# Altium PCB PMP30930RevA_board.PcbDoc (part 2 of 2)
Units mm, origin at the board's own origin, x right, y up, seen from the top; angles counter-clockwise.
Board outline 59.18 x 142.49 mm, 4 copper layers (Top Layer, Layer 1, Layer 2, Bottom Layer), stack 1.787 mm thick; 111 components, 60 nets, 253 pads, 640 vias.
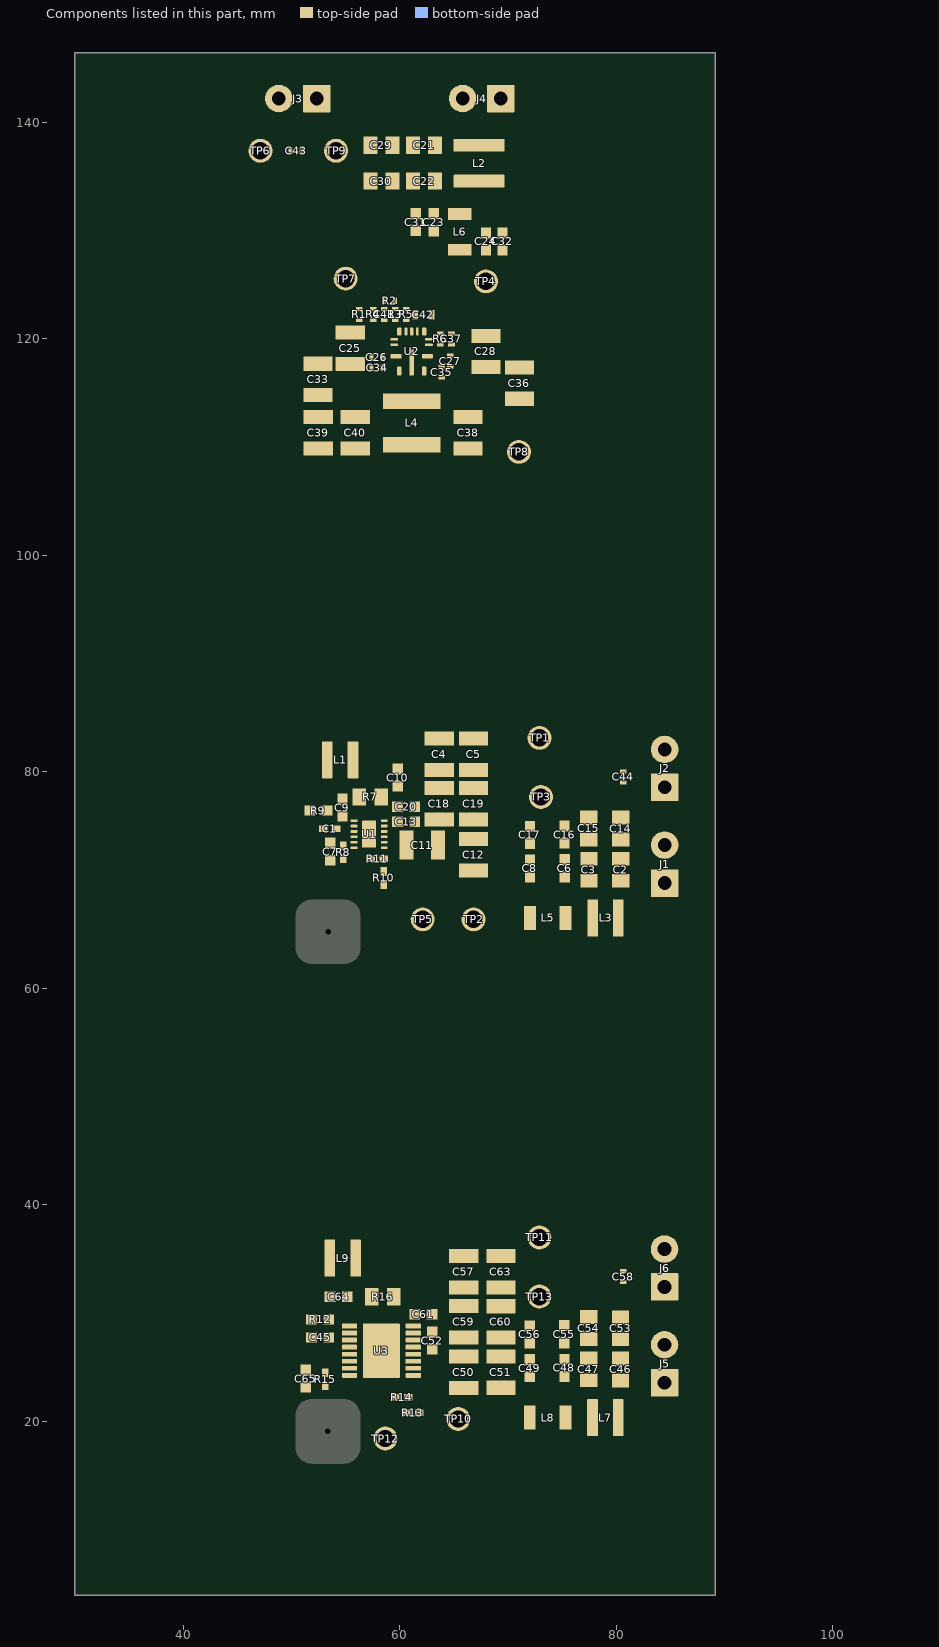
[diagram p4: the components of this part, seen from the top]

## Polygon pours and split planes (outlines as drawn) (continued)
NetC64_1 on Top Layer "NETC64_1_L01_P148" (solid, pour order 148): 54.455,28.056 cw(c55.096,28.773) 54.229,28.356 ccw(c53.617,27.745) 53.616,28.61 53.467,28.61 cw(c53.467,29.223) 53.033,28.79 52.884,28.938 cw(c53.318,29.372) 52.705,29.372 52.705,35.976 cw(c53.752,36.05) 52.959,36.738 cw(c53.336,36.354) 53.341,36.893 53.802,36.893 cw(c53.765,36.457) 54.1,36.738 cw(c53.31,36.049) 54.356,35.976 54.356,30.546 ccw(c55.656,30.546) 54.737,29.626 ccw(c55.35,30.239) 55.35,29.372 55.7,29.372 cw(c55.701,28.939) 56.007,29.245 56.044,29.208 cw(c55.828,28.992) 56.134,28.991 56.134,28.037 cw(c55.97,28.037) 56.086,27.921 cw(c56.001,28.005) 56.001,27.886 54.893,27.886 cw(c54.879,28.5)
GND_C on Top Layer "GND_C_L01_P147" (solid, pour order 147): 84.083,25.562 cw(c84.083,27.73) 82.55,26.197 82.237,26.51 cw(c83.321,27.594) 81.788,27.594 81.788,27.69 ccw(c80.487,27.69) 81.407,28.61 ccw(c81.1,28.304) 81.1,28.737 76.94,28.737 ccw(c76.94,27.87) 76.327,28.483 76.305,28.461 cw(c75.438,29.328) 75.438,28.102 72.092,28.102 cw(c72.092,29.836) 70.866,28.61 ccw(c70.586,28.367) 70.612,28.737 69.85,28.737 69.85,33.182 81.704,33.182 ccw(c81.704,34.917) 82.931,33.69 cw(c83.544,33.077) 83.544,33.944 85.493,33.944 cw(c85.493,33.077) 86.106,33.69 cw(c85.493,33.077) 86.36,33.077 86.36,26.863 cw(c85.059,26.863) 85.979,25.943 cw(c85.059,26.863) 85.059,25.562
NetC49_2 on Top Layer "NETC49_2_L01_P146" (solid, pour order 146): 71.538,25.172 cw(c71.559,25.258) 71.483,25.212 cw(c71.625,25.323) 71.447,25.347 71.447,27.731 cw(c71.553,27.723) 71.483,27.804 cw(c71.554,27.72) 71.564,27.829 72.466,27.829 cw(c72.459,27.714) 72.546,27.789 cw(c72.452,27.712) 72.573,27.698 72.573,25.333 cw(c72.405,25.33) 72.525,25.212 cw(c72.433,25.297) 72.437,25.172
NetC48_2 on Top Layer "NETC48_2_L01_P145" (solid, pour order 145): 74.792,25.126 cw(c74.792,25.272) 74.689,25.169 cw(c74.802,25.296) 74.632,25.286 74.632,27.754 cw(c74.738,27.746) 74.668,27.826 cw(c74.739,27.743) 74.748,27.852 75.651,27.852 cw(c75.643,27.737) 75.73,27.812 cw(c75.636,27.735) 75.757,27.721 75.759,25.248 cw(c75.644,25.257) 75.719,25.169 cw(c75.608,25.29) 75.6,25.126
NetC47_2 on Top Layer "NETC47_2_L01_P144" (solid, pour order 144): 77.597,28.356 76.751,28.356 ccw(c76.751,28.129) 76.591,28.29 ccw(c76.711,28.169) 76.541,28.169 76.541,25.229 ccw(c76.734,25.229) 76.598,25.093 ccw(c76.702,25.197) 76.702,25.05 78.224,25.05 ccw(c78.224,25.231) 78.352,25.103 ccw(c78.216,25.239) 78.409,25.239 78.409,28.133 ccw(c78.186,28.133) 78.343,28.291 ccw(c78.184,28.131) 78.184,28.357 78.141,28.357
NetC46_2 on Top Layer "NETC46_2_L01_P143" (solid, pour order 143): 80.518,28.356 79.672,28.356 ccw(c79.672,28.129) 79.512,28.29 ccw(c79.632,28.169) 79.462,28.169 79.462,25.229 ccw(c79.655,25.229) 79.519,25.093 ccw(c79.623,25.197) 79.623,25.05 81.145,25.05 ccw(c81.145,25.231) 81.273,25.103 ccw(c81.137,25.239) 81.33,25.239 81.33,28.133 ccw(c81.107,28.133) 81.264,28.291 ccw(c81.105,28.131) 81.105,28.357 81.062,28.357
NetC46_1 on Top Layer "NETC46_1_L01_P142" (solid, pour order 142): 79.808,24.673 ccw(c79.808,24.239) 79.502,24.546 ccw(c79.808,24.239) 79.375,24.239 79.375,18.884 ccw(c79.808,18.884) 79.502,18.577 ccw(c79.808,18.884) 79.808,18.45 81.625,18.45 ccw(c81.625,20.99) 83.421,19.194 85.598,21.371 ccw(c84.678,22.291) 85.979,22.291 85.979,24.62 ccw(c85.545,24.62) 85.852,24.927 ccw(c85.545,24.62) 85.545,25.054 82.274,25.054 ccw(c82.274,24.187) 81.661,24.8 cw(c81.354,25.107) 81.354,24.673
NetC47_1 on Top Layer "NETC47_1_L01_P141" (solid, pour order 141): 74.855,24.673 ccw(c74.855,24.24) 74.549,24.546 ccw(c74.855,24.24) 74.422,24.239 74.422,19.571 ccw(c75.289,19.571) 74.676,18.958 ccw(c75.861,20.084) 75.819,18.45 78.105,18.45 ccw(c78.079,18.82) 78.359,18.577 ccw(c78.116,18.857) 78.486,18.831 78.486,24.292 ccw(c78.116,24.266) 78.359,24.546 ccw(c78.052,24.24) 78.052,24.673
GND_C on Top Layer "GND_C_L01_P140" (solid, pour order 140): 61.428,27.914 61.853,27.914 ccw(c61.853,28.15) 62.02,27.983 ccw(c61.819,28.184) 62.103,28.184 62.103,30.208 cw(c62.665,30.262) 62.23,30.622 cw(c62.534,30.389) 62.484,30.769 63.246,30.769 cw(c63.252,29.975) 63.81,30.541 cw(c63.176,29.818) 64.135,29.88 64.135,29.604 ccw(c65.002,29.604) 64.389,28.991 ccw(c65.002,29.604) 65.002,28.737 72.136,28.737 72.136,33.182 59.107,33.182 ccw(c59.107,32.749) 58.801,33.055 ccw(c59.107,32.749) 58.674,32.748 58.674,30.568 cw(c58.241,30.567) 58.547,30.261 58.51,30.224 cw(c58.293,30.44) 58.293,30.134 57.382,30.134 ccw(c57.382,29.268) 56.769,29.88 ccw(c57.382,29.267) 56.515,29.267 56.515,23.53 59.944,23.53 59.944,24.06 cw(c60.807,24.057) 60.242,24.71 60.23,25.117 59.944,25.435 59.944,27.541 cw(c60.031,27.552) 59.962,27.606 cw(c60.513,27.301) 60.339,27.907 60.572,27.907
NetC50_2 on Top Layer "NETC50_2_L01_P139" (solid, pour order 139): 66.803,28.496 67.004,28.496 cw(c67.004,28.063) 67.311,28.369 67.348,28.332 cw(c67.131,28.115) 67.438,28.115 67.438,25.575 cw(c67.131,25.575) 67.348,25.358 67.311,25.321 cw(c67.004,25.628) 67.004,25.194 64.823,25.194 cw(c64.823,25.628) 64.517,25.321 64.48,25.358 cw(c64.696,25.575) 64.39,25.575 64.39,28.115 cw(c64.76,28.089) 64.517,28.369 cw(c64.797,28.126) 64.771,28.496 64.898,28.496
NetC51_2 on Top Layer "NETC51_2_L01_P138" (solid, pour order 138): 70.231,28.483 70.432,28.483 cw(c70.432,28.05) 70.739,28.356 70.776,28.319 cw(c70.559,28.102) 70.866,28.102 70.866,25.562 cw(c70.559,25.562) 70.776,25.345 70.739,25.308 cw(c70.432,25.615) 70.432,25.181 68.251,25.181 cw(c68.251,25.615) 67.945,25.308 67.908,25.345 cw(c68.124,25.562) 67.818,25.562 67.818,28.102 cw(c68.188,28.076) 67.945,28.356 cw(c68.225,28.113) 68.199,28.483 68.326,28.483
NetC49_1 on Top Layer "NETC49_1_L01_P137" (solid, pour order 137): 60.452,27.086 cw(c60.668,26.996) 60.579,27.213 63.754,27.213 cw(c63.728,26.844) 64.008,27.086 cw(c63.614,26.743) 64.135,26.705 64.135,25.308 ccw(c64.505,25.334) 64.262,25.054 ccw(c64.606,25.451) 64.643,24.927 72.263,24.927 cw(c72.058,24.125) 72.771,24.546 cw(c72.369,24.218) 72.885,24.164 72.885,19.72 cw(c72.37,19.667) 72.771,19.339 cw(c72.275,19.67) 72.39,19.085 65.695,19.085 cw(c65.695,21.625) 63.899,19.829 62.738,20.99 cw(c63.964,22.217) 62.23,22.217 62.23,24.695 ccw(c61.581,24.785) 62.103,25.181 ccw(c61.824,24.94) 61.849,25.308 60.557,25.308 cw(c60.632,25.488) 60.452,25.413
GND_C on Top Layer "GND_C_L01_P135" (solid, remove dead copper, pour order 135): 50.876,23.682 ccw(c50.876,23.124) 50.317,23.124 50.317,17.815 ccw(c50.952,17.815) 50.952,17.18 58.928,17.18 ccw(c58.928,18.196) 59.944,18.196 59.944,24.927 56.616,25.13 56.616,23.86 cw(c56.439,23.86) 56.439,23.682
NetC64_2 on Top Layer "NETC64_2_L01_P134" (solid, remove dead copper, pour order 134): 58.192,30.767 cw(c57.94,30.767) 57.94,30.515 55.132,30.515 cw(c55.132,30.978) 54.669,30.978 54.669,31.969 cw(c55.093,31.969) 55.093,32.393 57.989,32.393 cw(c57.989,32.19) 58.192,32.19
NetC52_2 on Top Layer "NETC52_2_L01_P133" (solid, pour order 133): 62.572,27.713 cw(c62.572,27.859) 62.469,27.756 cw(c62.582,27.883) 62.412,27.873 62.412,30.341 cw(c62.518,30.334) 62.448,30.414 cw(c62.519,30.33) 62.529,30.439 63.431,30.439 cw(c63.423,30.324) 63.511,30.4 cw(c63.416,30.322) 63.538,30.308 63.54,27.835 cw(c63.424,27.844) 63.499,27.756 cw(c63.388,27.877) 63.38,27.713
GND on Top Layer "NONET_L-01_P-001" (solid, pour order 129): 50.305,69.043 50.305,63.582 ccw(c51.702,63.582) 51.702,62.185 59.449,62.185 ccw(c59.449,63.455) 60.719,63.455 60.719,72.853 ccw(c59.068,72.853) 59.068,74.504 59.068,72.599 cw(c58.306,72.599) 58.306,71.837 56.655,71.837
GND on Top Layer "NONET_L-01_P-001" (solid, pour order 128): 75.705,79.33 71.55,79.33 cw(c71.55,81.87) 69.754,80.074 69.609,80.219 ccw(c68.076,78.686) 68.076,80.854 62.37,80.854 62.37,77.679 62.515,77.534 ccw(c64.311,79.33) 64.311,76.79 67.366,76.79 cw(c67.366,75.056) 68.593,76.282 69.451,75.424 ccw(c70.752,76.725) 70.752,74.885 75.705,74.885
GND on Top Layer "NONET_L-01_P-001" (solid, pour order 127): 57.798,74.504 57.798,75.012 cw(c58.941,75.012) 58.941,76.155 60.211,76.155 ccw(c60.211,76.536) 60.592,76.536 60.592,77.171 cw(c61.1,77.171) 61.1,77.679 68.212,77.679 68.212,80.854 62.422,80.854 ccw(c62.422,80.42) 62.116,80.727 61.168,79.779 cw(c60.084,80.863) 60.084,79.33 59.358,79.33 ccw(c59.358,76.79) 57.562,78.586 57.544,78.568 ccw(c57.85,78.261) 57.417,78.261 57.417,77.456 cw(c56.116,77.456) 57.036,76.536 ccw(c58.262,75.31) 56.528,75.31 56.528,74.504
NetC4_1 on Top Layer "NONET_L-01_P-001" (solid, pour order 125): 55.131,79.33 ccw(c55.512,79.33) 55.512,78.949 56.878,78.949 ccw(c56.878,80.25) 57.798,79.33 cw(c58.718,78.41) 58.718,79.711 60.158,79.711 ccw(c60.158,80.145) 60.465,79.838 61.209,80.582 cw(c62.615,78.984) 62.751,81.108 68.212,81.108 cw(c68.411,78.831) 69.881,80.582 ccw(c71.677,82.378) 71.677,79.838 81.463,79.838 ccw(c81.463,81.572) 82.69,80.346 cw(c82.996,80.039) 82.996,80.473 85.865,80.473 ccw(c85.865,80.981) 86.373,80.981 86.373,82.505 ccw(c83.833,82.505) 83.833,85.045 56.02,85.045 ccw(c56.02,84.156) 55.131,84.156
NetC8_1 on Top Layer "NONET_L-01_P-001" (solid, pour order 123): 63.132,71.583 cw(c63.121,72.476) 62.497,71.837 cw(c63.379,72.741) 62.116,72.726 62.116,73.816 ccw(c61.682,73.816) 61.989,74.123 61.75,74.362 ccw(c61.1,73.711) 61.1,74.631 ccw(c61.1,74.018) 60.666,74.451 59.957,73.742 59.957,71.973 ccw(c62.125,71.973) 60.592,70.44 65.055,65.977 ccw(c66.851,67.773) 66.851,65.233 72.35,65.233 ccw(c72.35,65.667) 72.657,65.36 ccw(c72.35,65.667) 72.784,65.667 72.784,70.514 ccw(c72.35,70.514) 72.657,70.821 72.62,70.858 ccw(c72.403,70.641) 72.403,70.948 71.672,70.948 cw(c71.672,72.249) 70.752,71.329 ccw(c70.139,70.716) 70.139,71.583
no net on Top Layer "NONET_L-01_P-001" (solid, pour order 122): 17.498,10.404
NetC11_2 on Top Layer "NONET_L-01_P-001" (solid, pour order 120): 64.783,76.409 cw(c64.783,76.155) 65.037,76.155 65.037,72.599 cw(c64.275,72.599) 64.275,71.837 63.005,71.837 cw(c63.005,72.091) 62.751,72.091 62.751,74.25 ccw(c62.37,74.25) 62.37,74.631 cw(c62.37,74.758) 62.243,74.758 62.243,76.155 cw(c62.497,76.155) 62.497,76.409
NetC8_1 on Top Layer "NONET_L-01_P-001" (solid, pour order 118): 58.306,75.647 cw(c58.982,74.88) 59.046,75.901 60.194,75.901 cw(c60.194,75.656) 60.367,75.829 60.471,75.726 cw(c60.084,75.339) 60.631,75.339 60.631,74.86 ccw(c60.825,74.854) 60.683,74.721 ccw(c60.936,75.024) 60.973,74.631 61.174,74.631 cw(c61.174,74.197) 61.481,74.504 cw(c61.174,74.197) 61.608,74.197 61.608,73.742 59.957,73.742 ccw(c59.65,73.742) 59.867,73.959 59.703,74.123 ccw(c59.09,73.51) 59.09,74.377 58.306,74.377
NetC13_2 on Top Layer "NETC13_2_L01_P000" (solid, pour order 0): 61.044,74.829 cw(c61.037,75.035) 60.896,74.884 cw(c61.029,75.02) 60.839,75.02 60.839,77.224 cw(c61.016,77.246) 60.875,77.356 cw(c60.996,77.248) 60.988,77.41 61.747,77.41 cw(c61.746,77.177) 61.912,77.34 cw(c61.803,77.221) 61.965,77.224 61.965,75.02 cw(c61.777,75.014) 61.912,74.884 cw(c61.777,75.022) 61.774,74.829
GND on Top Layer "GND_L01_P117" (solid, pour order 117): 50.332,68.696 50.332,69.861 cw(c52.872,69.861) 52.872,72.401 55.821,72.401 ccw(c55.821,73.107) 56.528,73.107 57.798,73.107 57.798,68.662
NetC1_2 on Top Layer "NETC1_2_L01_P116" (solid, pour order 116): 55.897,75.106 53.749,75.106 ccw(c53.749,75.021) 53.665,75.021 53.665,74.454 ccw(c53.73,74.454) 53.73,74.389 54.468,74.389 ccw(c54.468,74.704) 54.784,74.704 cw(c54.946,74.704) 54.946,74.867 55.897,74.867
NetC9_1 on Top Layer "NETC9_1_L01_P100" (solid, pour order 100): 55.523,75.356 53.263,75.356 cw(c53.319,75.79) 52.972,75.523 cw(c54.005,76.49) 52.591,76.536 52.591,82.378 cw(c53.259,82.413) 52.849,82.942 cw(c53.126,82.61) 53.167,83.04 53.569,83.04 cw(c53.575,82.699) 53.814,82.942 cw(c53.572,82.707) 53.91,82.7 53.91,77.14 ccw(c54.413,77.136) 54.055,76.783 ccw(c54.995,77.86) 55.091,76.434 cw(c55.184,75.277) 55.945,76.153 cw(c55.446,75.661) 56.147,75.647 cw(c55.794,75.593) 56.078,75.377
GND_B on Top Layer "GND_B_L01_P075" (solid, pour order 75): 61.862,116.467 ccw(c62.295,116.467) 61.989,116.16 62.063,116.086 ccw(c62.497,116.519) 62.497,115.906 62.974,115.906 cw(c62.974,114.605) 63.894,115.525 64.17,115.249 cw(c63.302,114.382) 64.529,114.382 64.529,112.608 ccw(c65.32,112.608) 64.76,112.049 ccw(c64.953,112.241) 64.953,111.969 71.557,111.969 ccw(c71.557,113.703) 72.784,112.477 ccw(c72.477,112.784) 72.911,112.784 72.911,115.853 ccw(c72.477,115.853) 72.784,116.16 ccw(c72.477,115.853) 72.477,116.287 66.973,116.287 cw(c66.973,117.588) 66.053,116.668 ccw(c65.44,116.055) 65.44,116.922 64.275,116.922 cw(c64.275,117.966) 63.537,117.228 63.224,117.541 ccw(c62.878,117.195) 62.878,117.684 62.111,117.684 ccw(c62.111,117.425) 61.929,117.608 ccw(c62.09,117.447) 61.862,117.447
GND_B on Top Layer "GND_B_L01_P109" (solid, pour order 109): 68.847,128.479 68.847,127.419 ccw(c70.581,127.419) 69.355,126.193 69.373,126.175 cw(c67.577,124.379) 70.117,124.379 70.117,119.97 ccw(c70.879,119.97) 70.879,119.208 72.276,119.208 ccw(c72.276,119.843) 72.911,119.843 72.911,128.098 ccw(c72.149,128.098) 72.149,128.86 69.228,128.86 ccw(c69.228,128.479)
NetC24_2 on Top Layer "NETC24_2_L01_P108" (solid, pour order 108): 67.401,129.425 ccw(c67.655,129.425) 67.655,129.171 69.814,129.171 ccw(c69.814,129.425) 70.068,129.425 70.068,130.314 ccw(c69.814,130.314) 69.814,130.568 67.655,130.568 ccw(c67.655,130.314) 67.401,130.314
NetC24_1 on Top Layer "NETC24_1_L01_P107" (solid, pour order 107): 64.402,123.816 ccw(c66.941,123.816) 65.146,122.02 65.291,121.875 cw(c64.984,121.568) 65.418,121.568 65.418,119.081 cw(c65.111,119.081) 65.328,118.864 65.164,118.7 cw(c65.062,118.801) 65.062,118.658 62.133,118.658 ccw(c62.122,118.086) 61.725,118.497 ccw(c62.017,118.213) 61.61,118.203 61.61,118.076 ccw(c61.761,118.076) 61.654,117.969 61.688,117.935 ccw(c61.777,118.023) 61.777,117.898 65.458,117.898 ccw(c65.458,119.243) 66.409,118.292 cw(c66.781,117.921) 66.781,118.446 68.435,118.446 ccw(c68.435,119.747) 69.355,118.827 ccw(c69.048,119.134) 69.482,119.134 69.482,124.66 ccw(c67.314,124.66) 68.847,126.193 cw(c69.766,127.113) 68.466,127.113 68.466,128.613 ccw(c68.12,128.613) 68.364,128.857 ccw(c68.186,128.679) 68.186,128.931 64.61,128.931 ccw(c64.597,128.722) 64.458,128.879 ccw(c64.574,128.751) 64.402,128.759
NetC23_2 on Top Layer "NETC23_2_L01_P106" (solid, pour order 106): 60.973,129.495 ccw(c61.227,129.495) 61.227,129.241 63.386,129.241 ccw(c63.386,129.495) 63.64,129.495 63.64,130.384 ccw(c63.386,130.384) 63.386,130.638 61.227,130.638 ccw(c61.227,130.384) 60.973,130.384
GND_B on Top Layer "GND_B_L01_P103" (solid, pour order 103): 58.052,138.258 cw(c60.338,138.258) 60.338,140.544 65.672,140.544 ccw(c65.672,142.068) 67.196,142.068 67.196,143.338 ccw(c66.18,143.338) 66.18,144.354 57.417,144.354 ccw(c57.417,143.338) 56.401,143.338 56.401,133.559 ccw(c58.941,133.559) 58.941,131.019 61.862,131.019 ccw(c61.862,131.273) 62.116,131.273 62.116,132.543 ccw(c61.481,132.543) 61.481,133.178 58.814,133.178 cw(c58.814,133.94) 58.052,133.94
GND_B on Top Layer "GND_B_L01_P102" (solid, pour order 102): 50.686,135.972 ccw(c51.956,135.972) 51.956,134.702 54.496,134.702 ccw(c54.496,135.718) 55.512,135.718 55.512,143.465 ccw(c54.623,143.465) 54.623,144.354 51.575,144.354 ccw(c51.575,143.465) 50.686,143.465
NetC24_1 on Top Layer "NETC24_1_L01_P092" (solid, pour order 92): 56.909,121.24 cw(c56.909,121.494) 56.655,121.494 56.655,121.875 ccw(c56.528,121.875) 56.528,122.002 54.115,122.002 ccw(c54.115,121.494) 53.607,121.494 53.607,119.462 ccw(c54.115,119.462) 54.115,118.954 56.909,118.954
NetC22_2 on Top Layer "NETC22_2_L01_P090" (solid, pour order 90): 58.56,133.813 ccw(c58.814,133.813) 58.814,133.559 61.862,133.559 ccw(c61.862,133.813) 62.116,133.813 62.116,135.337 ccw(c61.862,135.337) 61.862,135.591 58.814,135.591 ccw(c58.814,135.337) 58.56,135.337
NetC21_2 on Top Layer "NETC21_2_L01_P089" (solid, pour order 89): 58.56,137.115 ccw(c58.814,137.115) 58.814,136.861 61.862,136.861 ccw(c61.862,137.115) 62.116,137.115 62.116,138.639 ccw(c61.862,138.639) 61.862,138.893 58.814,138.893 ccw(c58.814,138.639) 58.56,138.639
NetC22_1 on Top Layer "NETC22_1_L01_P088" (solid, pour order 88): 69.863,133.432 cw(c67.323,133.432) 67.323,130.892 62.751,130.892 cw(c62.751,131.273) 62.37,131.273 62.37,135.21 cw(c62.751,135.21) 62.751,135.591 69.228,135.591 cw(c69.228,134.956) 69.863,134.956
no net on Top Layer "NONET_L01_P087" (solid, pour order 87): 24.955,38.105
NetC21_1 on Top Layer "NETC21_1_L01_P086" (solid, pour order 86): 72.911,141.814 ccw(c70.371,141.814) 70.371,144.354 68.593,144.354 ccw(c68.593,143.465) 67.704,143.465 67.704,141.433 cw(c66.434,141.433) 66.434,140.163 64.275,140.163 ccw(c64.275,138.512) 62.624,138.512 62.624,137.115 ccw(c63.005,137.115) 63.005,136.734 71.641,136.734 ccw(c71.641,138.004) 72.911,138.004
SW on Top Layer "SW_L01_P058" (solid, pour order 58): 61.354,117.176 ccw(c62.987,117.217) 61.862,116.033 ccw(c62.837,117.049) 62.867,115.641 cw(c62.966,114.392) 63.779,115.345 cw(c63.44,115.042) 63.894,115.017 63.894,113.8 cw(c63.46,113.8) 63.767,113.493 63.73,113.456 cw(c63.513,113.672) 63.513,113.366 58.739,113.366 cw(c58.739,113.799) 58.433,113.493 58.396,113.53 cw(c58.612,113.747) 58.306,113.747 58.306,114.785 cw(c58.828,114.822) 58.433,115.165 cw(c59.642,113.871) 59.703,115.641 ccw(c59.622,116.781) 60.487,116.033 ccw(c59.389,116.816) 60.719,117.039 60.719,118.866 cw(c60.969,118.866) 60.792,119.044 cw(c60.882,118.954) 60.882,119.081 61.256,119.081 cw(c61.237,118.862) 61.405,119.003 cw(c61.166,118.977) 61.354,118.827
NetC38_1 on Top Layer "NETC38_1_L01_P083" (solid, pour order 83): 67.323,110.953 cw(c67.323,110.064) 68.212,110.064 68.212,108.667 cw(c65.481,108.667) 65.481,105.936 48.019,105.936 cw(c48.019,110.699) 43.256,110.699 43.256,138.829 cw(c48.019,138.829) 48.019,143.592 48.781,143.592 cw(c48.781,142.195) 50.178,142.195 50.178,112.985 ccw(c52.21,112.985) 52.21,110.953
NetC28_2 on Top Layer "NETC28_2_L01_P078" (solid, pour order 78): 72.301,116.635 ccw(c72.301,116.762) 72.428,116.762 72.428,118.032 ccw(c72.301,118.032) 72.301,118.159 66.713,118.159 ccw(c66.713,118.032) 66.586,118.032 66.586,116.762 ccw(c66.713,116.762) 66.713,116.635
NetC25_2 on Top Layer "NETC25_2_L01_P074" (solid, pour order 74): 56.655,116.922 ccw(c56.655,117.049) 56.782,117.049 56.782,118.319 ccw(c56.655,118.319) 56.655,118.446 51.067,118.446 ccw(c51.067,118.319) 50.94,118.319 50.94,117.049 ccw(c51.067,117.049) 51.067,116.922
GND_B on Top Layer "GND_B_L01_P073" (solid, pour order 73): 61.277,120.692 61.277,121.003 cw(c61.972,121.003) 61.481,121.494 61.772,121.785 ccw(c61.555,122.002) 61.862,122.002 61.862,122.584 ccw(c61.428,122.584) 61.735,122.891 ccw(c61.122,122.278) 61.122,123.145 60.517,123.145 ccw(c60.517,122.711) 60.211,123.018 60.174,122.981 ccw(c60.39,122.764) 60.084,122.764 60.084,122.69 cw(c59.65,122.69) 59.957,122.383 58.538,122.383 cw(c58.538,123.25) 57.925,122.637 57.798,122.764 57.29,122.764 ccw(c57.404,122.65) 57.242,122.65 57.242,122.571 ccw(c57.583,122.571) 57.342,122.33 57.417,122.256 ccw(c57.723,122.563) 57.723,122.129 60.666,122.129 cw(c60.666,121.695) 60.973,122.002 61.01,121.965 cw(c60.793,121.748) 61.1,121.748 61.1,121.674 cw(c60.666,121.674) 60.973,121.367 ccw(c61.111,121.229) 60.915,121.229 60.915,120.459 ccw(c61.09,120.459) 60.967,120.335 60.975,120.327 61.188,120.327 ccw(c61.188,120.393) 61.235,120.347 61.247,120.359 ccw(c61.176,120.43) 61.276,120.43
NetC24_1 on Top Layer "NETC24_1_L01_P072" (solid, pour order 72): 58.306,117.938 cw(c58.306,118.244) 58.089,118.028 58.015,118.102 cw(c58.231,118.318) 57.925,118.319 57.925,118.393 ccw(c57.491,118.393) 57.798,118.7 57.723,118.774 ccw(c57.29,118.341) 57.29,118.954 54.115,118.954 54.115,121.24 56.782,121.24 cw(c56.804,119.453) 58.052,120.732 cw(c57.061,119.328) 58.754,119.62 ccw(c59.399,119.714) 59.01,119.191 ccw(c59.361,119.662) 59.449,119.081 59.904,119.081 cw(c59.904,118.647) 60.211,118.954 60.248,118.917 cw(c60.031,118.7) 60.338,118.7 60.338,118.372 cw(c59.904,118.372) 60.211,118.065 60.174,118.028 cw(c59.957,118.244) 59.957,117.938
GND_B on Top Layer "GND_B_L01_P062" (solid, pour order 62): 59.703,117.683 58.306,117.683 58.199,117.683 ccw(c58.673,117.099) 57.925,117.176 cw(c57.292,117.246) 57.279,116.61 51.274,116.61 ccw(c51.463,115.974) 50.813,116.107 50.813,112.477 ccw(c51.182,112.503) 50.94,112.223 ccw(c51.563,112.859) 51.575,111.969 57.036,111.969 ccw(c56.921,112.554) 57.375,112.168 ccw(c56.935,112.589) 57.544,112.604 57.544,113.711 cw(c60.082,113.712) 58.288,115.507 58.306,115.525 cw(c59.4,114.183) 59.576,115.906 ccw(c59.588,116.797) 60.211,116.16 ccw(c59.419,116.847) 60.465,116.922 60.465,117.123 ccw(c59.815,117.034) 60.211,117.557 ccw(c59.932,117.313) 59.957,117.683
no net on Top Layer "NONET_L01_P066" (solid, pour order 66): 69.192,38.582
no net on Top Layer "NONET_L01_P064" (solid, pour order 64): 69.151,38.613
SW on Top Layer "SW_L01_P063" (solid, pour order 63): 64.529,119.716 64.48,119.716 ccw(c64.48,119.611) 64.375,119.611 64.375,119.308 cw(c64.148,119.308) 64.148,119.081 61.227,119.081 ccw(c61.227,118.954) 61.1,118.954 61.1,118.573 61.354,118.319 cw(c61.798,118.382) 61.735,118.827 64.644,118.827 ccw(c64.644,119.312) 65.128,119.312 65.128,119.63 ccw(c65.043,119.63) 65.043,119.716
NetC3_1 on Top Layer "NETC3_1_L01_P045" (solid, pour order 45): 74.868,70.821 ccw(c74.868,70.387) 74.562,70.694 ccw(c74.868,70.387) 74.435,70.387 74.435,65.719 ccw(c75.302,65.719) 74.689,65.106 ccw(c75.873,66.232) 75.832,64.598 78.118,64.598 ccw(c78.091,64.968) 78.372,64.725 ccw(c78.129,65.005) 78.499,64.979 78.499,70.44 ccw(c78.129,70.414) 78.372,70.694 ccw(c78.065,70.388) 78.065,70.821
GND on Top Layer "GND_L01_P052" (solid, pour order 52): 84.096,71.71 cw(c84.096,73.878) 82.563,72.345 82.25,72.658 cw(c83.334,73.742) 81.801,73.742 81.801,73.838 ccw(c80.5,73.838) 81.42,74.758 ccw(c81.113,74.451) 81.113,74.885 76.953,74.885 ccw(c76.953,74.018) 76.34,74.631 76.318,74.609 cw(c75.451,75.476) 75.451,74.25 72.105,74.25 cw(c72.105,75.984) 70.879,74.758 ccw(c70.599,74.515) 70.625,74.885 69.863,79.33 81.717,79.33 ccw(c81.717,81.064) 82.944,79.838 cw(c83.557,79.225) 83.557,80.092 85.506,80.092 cw(c85.506,79.225) 86.119,79.838 cw(c85.506,79.225) 86.373,79.225 86.373,73.011 cw(c85.072,73.011) 85.992,72.091 cw(c85.072,73.011) 85.072,71.71
NetC8_2 on Top Layer "NETC8_2_L01_P051" (solid, pour order 51): 71.551,71.32 cw(c71.572,71.406) 71.496,71.36 cw(c71.638,71.471) 71.46,71.495 71.46,73.879 cw(c71.566,73.871) 71.496,73.951 cw(c71.567,73.868) 71.577,73.977 72.479,73.977 cw(c72.472,73.862) 72.559,73.937 cw(c72.465,73.86) 72.586,73.846 72.586,71.48 cw(c72.418,71.478) 72.538,71.36 cw(c72.446,71.445) 72.45,71.32
NetC6_2 on Top Layer "NETC6_2_L01_P050" (solid, pour order 50): 74.805,71.274 cw(c74.805,71.42) 74.702,71.316 cw(c74.815,71.444) 74.645,71.434 74.645,73.902 cw(c74.751,73.894) 74.681,73.974 cw(c74.752,73.891) 74.761,74 75.664,74 cw(c75.656,73.885) 75.743,73.96 cw(c75.649,73.883) 75.77,73.869 75.772,71.396 cw(c75.656,71.405) 75.732,71.316 cw(c75.621,71.437) 75.613,71.274
NetC3_2 on Top Layer "NETC3_2_L01_P049" (solid, pour order 49): 77.61,74.504 76.764,74.504 ccw(c76.764,74.277) 76.604,74.437 ccw(c76.724,74.317) 76.554,74.317 76.554,71.377 ccw(c76.747,71.377) 76.611,71.241 ccw(c76.715,71.345) 76.715,71.197 78.237,71.197 ccw(c78.237,71.379) 78.365,71.251 ccw(c78.229,71.387) 78.422,71.387 78.422,74.281 ccw(c78.199,74.281) 78.356,74.438 ccw(c78.197,74.279) 78.197,74.505 78.154,74.505
NetC2_2 on Top Layer "NETC2_2_L01_P048" (solid, pour order 48): 80.531,74.504 79.685,74.504 ccw(c79.685,74.277) 79.525,74.437 ccw(c79.645,74.317) 79.475,74.317 79.475,71.377 ccw(c79.668,71.377) 79.532,71.241 ccw(c79.636,71.345) 79.636,71.197 81.158,71.197 ccw(c81.158,71.379) 81.286,71.251 ccw(c81.15,71.387) 81.343,71.387 81.343,74.281 ccw(c81.12,74.281) 81.277,74.438 ccw(c81.118,74.279) 81.118,74.505 81.075,74.505
NetC2_1 on Top Layer "NETC2_1_L01_P047" (solid, pour order 47): 79.821,70.821 ccw(c79.821,70.387) 79.515,70.694 ccw(c79.821,70.387) 79.388,70.387 79.388,65.032 ccw(c79.821,65.032) 79.515,64.725 ccw(c79.821,65.032) 79.821,64.598 81.638,64.598 ccw(c81.638,67.138) 83.434,65.342 85.611,67.519 ccw(c84.691,68.439) 85.992,68.439 85.992,70.768 ccw(c85.558,70.768) 85.865,71.075 ccw(c85.558,70.768) 85.558,71.202 82.287,71.202 ccw(c82.287,70.335) 81.674,70.948 cw(c81.367,71.255) 81.367,70.821
no net on Top Layer "NONET_L01_P043" (solid, pour order 43): 12.763,12.832
NetC12_2 on Top Layer "NETC12_2_L01_P039" (solid, pour order 39): 67.726,76.328 67.927,76.328 cw(c67.927,75.894) 68.234,76.201 68.271,76.164 cw(c68.054,75.947) 68.361,75.947 68.361,73.407 cw(c68.054,73.407) 68.271,73.19 68.234,73.153 cw(c67.927,73.459) 67.927,73.026 65.747,73.026 cw(c65.747,73.459) 65.44,73.153 65.403,73.19 cw(c65.62,73.407) 65.313,73.407 65.313,75.947 cw(c65.683,75.92) 65.44,76.201 cw(c65.72,75.958) 65.694,76.328 65.821,76.328
no net on Top Layer "NONET_L01_P038" (solid, pour order 38): 21.907,13.34
no net on Top Layer "NONET_L01_P037" (solid, pour order 37): 22.034,13.34
NetC9_2 on Top Layer "NETC9_2_L01_P014" (solid, remove dead copper, pour order 14): 57.022,77.024 cw(c56.721,77.024) 56.721,76.723 54.62,76.723 cw(c54.62,77.186) 54.157,77.186 54.157,78.177 cw(c54.581,78.177) 54.581,78.601 56.721,78.601 cw(c56.721,78.3) 57.022,78.3
no net on Top Layer "NONET_L01_P002" (solid, remove dead copper, pour order 2): 46.189,25.04
GND_B on Bottom Layer "NONET_L-01_P-001" (solid, pour order 156): 31.75,101.6 ccw(c33.02,101.6) 33.02,100.33 86.36,100.33 ccw(c86.36,101.6) 87.63,101.6 87.63,144.399 ccw(c86.36,144.399) 86.36,145.669 33.274,145.669 ccw(c33.274,144.145) 31.75,144.145
GND on Bottom Layer "NONET_L-01_P-001" (solid, pour order 151): 31.75,53.594 ccw(c33.02,53.594) 33.02,52.324 86.36,52.324 ccw(c86.36,53.594) 87.63,53.594 87.63,96.774 ccw(c86.36,96.774) 86.36,98.044 33.02,98.044 ccw(c33.02,96.774) 31.75,96.774
GND_C on Bottom Layer "NONET_L-01_P-001" (solid, pour order 150): 31.75,6.35 ccw(c33.02,6.35) 33.02,5.08 86.36,5.08 ccw(c86.36,6.35) 87.63,6.35 87.63,49.53 ccw(c86.36,49.53) 86.36,50.8 33.02,50.8 ccw(c33.02,49.53) 31.75,49.53
no net on Bottom Layer "NONET_L04_P016" (solid, remove dead copper, pour order 16): 46.047,15.964
GND_B on Layer 2 "NONET_L-01_P-001" (solid, pour order 158): 86.36,145.669 cw(c86.36,144.399) 87.63,144.399 87.63,101.6 cw(c86.36,101.6) 86.36,100.33 33.02,100.33 cw(c33.02,101.6) 31.75,101.6 31.75,144.145 cw(c33.274,144.145) 33.274,145.669
GND on Layer 2 "NONET_L-01_P-001" (solid, pour order 152): 86.36,98.044 cw(c86.36,96.774) 87.63,96.774 87.63,53.594 cw(c86.36,53.594) 86.36,52.324 33.02,52.324 cw(c33.02,53.594) 31.75,53.594 31.75,96.774 cw(c33.02,96.774) 33.02,98.044
NetC24_1 on Layer 2 "NETC24_1_L03_P085" (solid, pour order 85): 66.815,117.938 ccw(c67.005,120.795) 69.863,120.605 69.863,125.177 ccw(c67.767,125.113) 67.704,127.209 54.496,127.209 ccw(c54.496,125.304) 52.591,125.304 52.591,120.478 ccw(c55.131,120.478) 55.131,117.938
GND_B on Layer 1 "NONET_L-01_P-001" (solid, pour order 157): 33.274,145.669 ccw(c33.274,144.145) 31.75,144.145 31.75,101.6 ccw(c33.02,101.6) 33.02,100.33 86.36,100.33 ccw(c86.36,101.6) 87.63,101.6 87.63,144.399 ccw(c86.36,144.399) 86.36,145.669
GND on Layer 1 "NONET_L-01_P-001" (solid, pour order 154): 86.36,98.044 cw(c86.36,96.774) 87.63,96.774 87.63,53.594 cw(c86.36,53.594) 86.36,52.324 33.02,52.324 cw(c33.02,53.594) 31.75,53.594 31.75,96.774 cw(c33.02,96.774) 33.02,98.044

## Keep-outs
Keep-Out Layer:
  text ".Layer_Name" at 14.465,-22.689 h0.9

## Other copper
Top Layer:
  text ".Layer_Name" at 14.465,-22.689 h0.9
Layer 1:
  pour cut-out: 50.292,82.169
  pour cut-out: 52.197,85.217 ccw(c52.197,83.82) 50.8,83.82 50.8,75.565 ccw(c52.197,75.565) 52.197,74.168 54.864,74.168 ccw(c54.864,75.692) 56.388,75.692 cw(c57.023,75.692) 57.023,76.327 ccw(c57.023,76.708) 57.404,76.708 57.404,83.82 ccw(c56.007,83.82) 56.007,85.217
  pour cut-out: 62.624,137.623 62.624,129.495 ccw(c64.783,129.495) 64.783,127.336 67.577,127.336 ccw(c67.577,129.876) 70.117,129.876 70.117,137.623 ccw(c68.466,137.623) 68.466,139.274 64.275,139.274 ccw(c64.275,137.623)
  pour cut-out: 63.894,110.953 ccw(c63.894,111.588) 64.529,111.588 64.529,114.509 ccw(c63.259,114.509) 63.259,115.779 62.751,115.779 cw(c62.751,116.922) 61.608,116.922 61.608,118.954 ccw(c61.354,118.954) 61.354,119.208 60.846,119.208 ccw(c60.846,118.954) 60.592,118.954 60.592,116.922 cw(c59.322,116.922) 59.322,115.652 59.068,115.652 ccw(c59.068,114.255) 57.671,114.255 57.671,111.588 ccw(c58.306,111.588) 58.306,110.953
Layer 2:
  pour cut-out: 106.553,74.676
  pour cut-out: 52.197,85.217 ccw(c52.197,83.82) 50.8,83.82 50.8,75.565 ccw(c52.197,75.565) 52.197,74.168 54.864,74.168 ccw(c54.864,75.692) 56.388,75.692 cw(c57.028,75.692) 57.028,76.332 57.077,76.332 ccw(c57.077,76.658) 57.404,76.658 57.404,83.82 ccw(c56.007,83.82) 56.007,85.217
Bottom Layer:
  pour cut-out: 52.197,85.217 ccw(c52.197,83.82) 50.8,83.82 50.8,75.565 ccw(c52.197,75.565) 52.197,74.168 54.864,74.168 ccw(c54.864,75.692) 56.388,75.692 cw(c57.023,75.692) 57.023,76.327 ccw(c57.023,76.708) 57.404,76.708 57.404,83.82 ccw(c56.007,83.82) 56.007,85.217
  pour cut-out: 52.07,39.37 ccw(c52.07,38.1) 50.8,38.1 50.8,27.686 ccw(c51.816,27.686) 51.816,26.67 55.626,26.67 ccw(c55.626,27.559) 56.515,27.559 56.515,28.702 cw(c57.912,28.702) 57.912,30.099 ccw(c57.912,30.607) 58.42,30.607 58.42,38.1 ccw(c57.15,38.1) 57.15,39.37
  text ".Layer_Name" at 14.465,-22.689 h0.9

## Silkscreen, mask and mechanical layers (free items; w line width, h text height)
Top Overlay:
  lines w0.254: 52.972,122.51 55.639,122.51 ; 56.274,132.797 60.465,132.797 60.973,133.305 ; 57.544,116.16 58.306,116.16 58.814,116.668 ; 61.227,78.06 61.227,81.362 ; 64.783,116.287 65.291,115.779 65.291,115.271 ; 65.418,116.922 65.926,116.414 65.926,116.16
  text "GND" at 60.211,143.211 h0.9 r180
  text "VIN" at 72.784,141.941 h0.9 r90
  text "VOUT" at 46.114,140.798 h0.9 r90
  text "9/2020" at 44.45,132.842 h0.9 r90
  text "PART C" at 44.45,124.587 h0.9 r90
  text "'.PRJ_Number' '.PCB_Rev'" at 44.45,109.474 h0.9 r90
  text "VOUT" at 84.595,84.791 h0.9
  text "GND" at 83.198,75.459 h0.9
  text "VIN" at 84.849,65.614 h0.9
  text "9/2020" at 82.055,62.82 h0.9
  text "'.PRJ_Number' '.PCB_Rev'" at 57.29,62.693 h0.9
  text "PART B" at 68.847,62.693 h0.9
  text "'.PRJ_Number' '.PCB_Rev'" at 56.642,38.77 h0.9
  text "VOUT" at 84.582,38.643 h0.9
  text "PART A" at 57.658,36.957 h0.9
  text "GND" at 83.185,29.311 h0.9
  text "VIN" at 84.836,19.466 h0.9
  text "9/2020" at 80.899,15.402 h0.9
  text ".Layer_Name" at 14.465,-22.689 h0.9
Bottom Overlay:
  text ".Layer_Name" at 14.465,-22.689 h0.9
Top Paste:
  text ".Layer_Name" at 14.465,-22.689 h0.9
Bottom Paste:
  text ".Layer_Name" at 14.465,-22.689 h0.9
Top Solder:
  text ".Layer_Name" at 14.465,-22.689 h0.9
  text ".Layer_Name" at 14.465,-22.689 h0.9
Bottom Solder:
  text "'.PRJ_Number' '.PCB_Rev'" at 76.975,81.489 h0.9 r90
  text "'.PRJ_Number' '.PCB_Rev'" at 77.152,35.946 h0.9 r90
  text ".Layer_Name" at 14.465,-22.689 h0.9
Drill Guide:
  text ".Layer_Name" at 14.465,-22.689 h0.9
M1 Board Outline:
  lines w0.254: 48.527,58.039 48.527,58.052 ; 89.154,51.4 89.154,50.073 ; 89.154,51.435 89.154,98.933 89.154,146.431 29.972,146.431 29.972,3.937 89.154,3.937 89.154,50.073 ; 89.154,50.073 89.154,50.073
  lines w0.3: 132.016,-0.884 132.143,-0.757
  text ".Layer_Name" at 14.465,-22.689 h0.9
M2 Board Dimensions:
  rectangle: 2.984,-11.044 12.509,-7.869
  rectangle: -0.191,-7.869 2.984,-4.694
  lines w0.178: -0.191,-7.869 25.209,-7.869 ; 2.984,-11.044 2.984,-4.694 ; 6.159,-11.044 6.159,-4.694 ; 12.509,-11.044 12.509,-4.694 ; 18.859,-11.044 18.859,-4.694 ; -0.191,-11.044 -0.191,-4.694 25.209,-4.694 25.209,-11.044 -0.191,-11.044
  text ".Layer_Name" at 14.465,-22.689 h0.9
M3 3D STEP Top:
  text ".Layer_Name" at 14.465,-22.689 h0.9
M4 3D STEP Bottom:
  text ".Layer_Name" at 14.465,-22.689 h0.9
M5 Assembly Top:
  lines w0.254: -7.608,-24.51 160.032,-24.51 ; -7.608,-19.345 160.083,-19.345 ; -7.608,-14.181 -7.608,-29.675 94.119,-29.675 160.083,-29.675 160.083,-14.181 -7.595,-14.181 -7.595,-29.675 32.423,-29.675 ; 55.003,-29.675 55.003,-14.181 ; 87.185,-19.345 87.185,-14.181 ; 108.521,-19.345 108.521,-14.181 ; 124.32,-29.84 124.32,-24.688
  text "COMPONENTS MARKED 'DNP' SHOULD NOT BE POPULATED." at 29.108,-8.974 h0.9
  text "ASSEMBLY VARIANT:" at 29.095,-11.907 h0.9
  text ".VariantName" at 55.41,-11.907 h0.9
  text "PCB VIEWED FROM TOP SIDE" at -5.995,-17.538 h0.9
  text "BOARD #:" at 56.908,-17.538 h0.9
  text ".PRJ_Number" at 70.764,-17.538 h0.9
  text "REV:" at 92.214,-17.538 h0.9
  text ".PCB_Rev" at 99.619,-17.538 h0.9
  text "SVN REV:" at 113.5,-17.538 h0.9
  text ".VersionControl_RevNumber" at 126.352,-17.538 h0.9
  text "TID #:" at 56.908,-22.702 h0.9
  text ".TID" at 70.764,-22.702 h0.9
  text "PLOT NAME =" at -5.995,-27.918 h0.9
  text ".plot_File_Name" at 14.465,-27.918 h0.9
  text "GENERATED    :" at 56.959,-27.918 h0.9
  text ".Print_Date" at 79.045,-27.918 h0.9
  text ".Print_Time" at 97.561,-27.918 h0.9
  text "TEXAS INSTRUMENTS" at 129.679,-27.918 h0.9
M6 Assembly Bottom:
  lines w0.254: -7.62,-19.358 160.071,-19.358 ; -7.569,-24.523 160.071,-24.523 ; 28.143,-29.852 28.143,-24.7 ; 43.942,-19.358 43.942,-14.193 ; 65.278,-19.358 65.278,-14.193 ; 97.46,-29.687 97.46,-14.193 ; 120.04,-29.687 160.058,-29.687 160.058,-14.193 -7.62,-14.193 -7.62,-29.687 58.344,-29.687 160.071,-29.687 160.071,-14.193
  text "COMPONENTS MARKED 'DNP' SHOULD NOT BE POPULATED." at 154.8,-8.961 h0.9
  text ".VariantName" at 128.282,-11.907 h0.9
  text "ASSEMBLY VARIANT:" at 154.673,-11.907 h0.9
  text ".VersionControl_RevNumber" at 26.111,-17.55 h0.9
  text "SVN REV:" at 38.963,-17.55 h0.9
  text ".PCB_Rev" at 52.844,-17.55 h0.9
  text "REV:" at 60.249,-17.55 h0.9
  text ".PRJ_Number" at 81.699,-17.55 h0.9
  text "BOARD #:" at 95.555,-17.55 h0.9
  text "PCB VIEWED FROM BOTTOM SIDE" at 158.458,-17.55 h0.9
  text ".TID" at 81.699,-22.715 h0.9
  text "TID #:" at 95.555,-22.715 h0.9
  text "TEXAS INSTRUMENTS" at 22.784,-27.93 h0.9
  text ".Print_Time" at 54.902,-27.93 h0.9
  text ".Print_Date" at 73.418,-27.93 h0.9
  text "GENERATED    :" at 95.504,-27.93 h0.9
  text ".plot_File_Name" at 137.998,-27.93 h0.9
  text "PLOT NAME =" at 158.458,-27.93 h0.9
M9 Title Sheet:
  drawing of 57 lines, arcs and shapes, not listed
  text "1" at 18.601,203.243 h0.9
  text "2" at 81.991,203.243 h0.9
  text "3" at 145.22,203.243 h0.9
  text "4" at 208.89,203.243 h0.9
  text "5" at 272.364,203.243 h0.9
  text "6" at 335.991,203.243 h0.9
  text "A" at -10.77,174.211 h0.9
  text "A" at 365.15,174.211 h0.9
  text "B" at -10.77,113.759 h0.9
  text "B" at 365.15,113.759 h0.9
  text "C" at -10.77,53.434 h0.9
  text "C" at 365.15,53.434 h0.9
  text "PROJECT TITLE:" at 287.934,6.165 h0.9
  text ".PRJ_Title" at 289.204,2.778 h0.9
  text "DESIGNED FOR:" at 287.934,-1.481 h0.9
  text ".PRJ_Customer" at 289.204,-5.037 h0.9
  text "D" at -10.77,-6.764 h0.9
  text "D" at 365.15,-6.764 h0.9
  text "FILE NAME:" at 287.934,-9.101 h0.9
  text ".PCB_File_Name_No_Path" at 289.204,-12.149 h0.9
  text "Texas Instruments (TI) and/or its licensors do not warrant the accuracy or completeness of this specification" at 161.709,-16.259 h0.9
  text "ENGINEER:" at 287.934,-16.467 h0.9
  text "LAYOUT BY:" at 326.161,-16.467 h0.9
  text "or any information contained therein. TI and/or its licensors do not warrant that this design will meet" at 160.566,-19.121 h0.9
  text ".PRJ_Engineer" at 289.204,-20.403 h0.9
  text ".PCB_Layout" at 327.444,-20.403 h0.9
  text "the specifications, will be suitable for your application or fit for any particular purpose, or will operate in" at 160.566,-21.983 h0.9
  text ".Layer_Name" at 14.465,-22.689 h0.9
  text "ALTIUM DESIGNER VERSION:" at 326.161,-24.341 h0.9
  text "an implementation. TI and/or its licensors do not warrant that the design is production worthy. You should" at 160.566,-24.844 h0.9
  text "completely validate and test your design implementation to confirm the system functionality for your application." at 161.709,-27.706 h0.9
  text ".print_Scale" at 289.204,-27.727 h0.9
  text ".Application_BuildNumber" at 327.444,-27.727 h0.9
  text "1" at 18.601,-32.977 h0.9
  text "2" at 81.991,-32.977 h0.9
  text "3" at 145.22,-32.977 h0.9
  text "4" at 208.89,-32.977 h0.9
  text "5" at 272.364,-32.977 h0.9
  text "6" at 335.991,-32.977 h0.9
M10 Fab Notes:
  drawing of 173 lines, arcs and shapes, not listed
  text "DESIGN INFORMATION" at 314.185,156.622 h0.9
  text "MIN. TRACK WIDTH:" at 297.814,152.05 h0.9
  text "8" at 325.658,152.05 h0.9
  text "MIL" at 329.589,152.05 h0.9
  text "MIN. CLEARANCE:" at 297.814,148.697 h0.9
  text "0.2" at 324.134,148.697 h0.9
  text "mm" at 329.589,148.697 h0.9
  text "MIN. VIA PAD SIZE:" at 297.814,145.344 h0.9
  text "24" at 324.896,145.344 h0.9
  text "MIL" at 329.589,145.344 h0.9
  text "0.05mm (2MIL)" at 315.467,141.745 h0.9
  text "MINIMUM ANNULAR RING" at 289.451,141.636 h0.9
  text "EXTERNAL" at 333.45,141.636 h0.9
  text "PER" at 294.531,138.639 h0.9
  text "IPC-D-275 CLASS 2 LEVEL C" at 300.119,138.639 h0.9
  text "MIL, HOLES" at 337.92,135.786 h0.9
  text "+/-" at 327.952,135.768 h0.9
  text "+/-" at 349.643,135.768 h0.9
  text "REGISTRATION TOLERANCES:" at 289.451,135.641 h0.9
  text "METAL" at 319.925,135.641 h0.9
  text "5" at 334.561,135.641 h0.9
  text "3" at 355.719,135.641 h0.9
  text "MIL" at 358.672,135.641 h0.9
  text "+/-" at 349.643,132.771 h0.9
  text "HOLE SIZE TOLERANCE (UNLESS OTHERWISE SPECIFIED):" at 289.451,132.644 h0.9
  text "3" at 355.719,132.644 h0.9
  text "MIL" at 358.672,132.644 h0.9
  text "MATERIAL:" at 287.552,127.324 h0.9
  text "FR-4 High Tg" at 312.608,123.759 h0.9
  text "FR-408" at 298.246,123.542 h0.9
  text "OTHER" at 336.041,123.542 h0.9
  text "X" at 308.673,123.449 h0.9
  text "62 MIL (1.6mm) +/-10%" at 306.376,119.409 h0.9
  text "THICKNESS:" at 289.451,119.3 h0.9
  text "X" at 303.121,119.3 h0.9
  text "OTHER" at 339.013,119.3 h0.9
  text "TOLERANCE:" at 289.451,115.287 h0.9
  text "X" at 310.77,115.287 h0.9
  text "ANSI IPC-6012 TYPE 3 CLASS 2" at 315.518,115.287 h0.9
  text "OTHER +/-" at 315.517,111.324 h0.9
  text "BOW & TWIST:" at 289.451,107.337 h0.9
  text "X" at 310.77,107.337 h0.9
  text "ANSI IPC-6012 TYPE 3 CLASS 2" at 315.518,107.337 h0.9
  text "OTHER +/-" at 315.517,103.311 h0.9
  text "DRILLING:" at 287.552,99.793 h0.9
  text "REFERENCE:" at 289.451,96.821 h0.9
  text "X" at 305.916,96.821 h0.9
  text "AS SHOWN" at 310.666,96.821 h0.9
  text "X" at 328.802,96.821 h0.9
  text "NC_DRILL FILES" at 332.281,96.821 h0.9
  text "PTH COPPER THICKNESS:" at 289.451,92.808 h0.9
  text "X" at 318.159,92.808 h0.9
  text "20-30 um" at 321.639,92.808 h0.9
  text "OTHER" at 339.851,92.808 h0.9
  text "BOARD FINISH:" at 287.552,88.769 h0.9
  text "SILKSCREEN:" at 291.495,85.772 h0.9
  text "X" at 315.594,85.772 h0.9
  text "TOP" at 318.794,85.772 h0.9
  text "X" at 328.548,85.772 h0.9
  text "BOTTOM" at 331.773,85.772 h0.9
  text "SILKSCREEN COLOR:" at 291.495,81.53 h0.9
  text "X" at 315.567,81.53 h0.9
  text "WHITE" at 318.794,81.53 h0.9
  text "OTHER" at 331.773,81.53 h0.9
  text "X" at 318.895,77.487 h0.9
  text "GREEN" at 322.121,77.487 h0.9
  text "OTHER" at 337.819,77.487 h0.9
  text "SOLDER RESIST COLOR:" at 291.495,77.212 h0.9
  text "X" at 318.895,73.169 h0.9
  text "MATTE" at 322.121,73.169 h0.9
  text "SEMI-GLOSS" at 337.807,73.152 h0.9
  text "IMMERSION GOLD (ENIG)" at 314.501,68.38 h0.9
  text "ENEPIG" at 348.475,68.297 h0.9
  text "SURFACE FINISH:" at 287.552,68.271 h0.9
  text "X" at 309.753,68.271 h0.9
  text "IMM. TIN/SILVER OR EQUIV" at 295.922,64.284 h0.9
  text "OTHER" at 332.281,64.284 h0.9
  text "ARRAY/PANEL:" at 287.552,59.737 h0.9
  text "CUT AND TRIM PER M1 BOARD OUTLINE" at 314.502,59.628 h0.9
  text "N.C. ROUTE" at 314.501,55.775 h0.9
  text "X" at 331.748,55.775 h0.9
  text "V. SCORE" at 336.498,55.775 h0.9
  text "CERTIFICATION:" at 287.552,52.295 h0.9
  text "MATERIALS AND WORKMANSHIP FOR ALL PCBS" at 305.967,52.295 h0.9
  text "TO MEET OR EXCEED THE REQUIREMENTS OF:" at 305.967,49.806 h0.9
  text "X" at 296.48,46.338 h0.9
  text "ANSI IPC-A-600F CLASS ->" at 300.011,46.338 h0.9
  text "X" at 341.643,46.338 h0.9
  text "2" at 344.664,46.338 h0.9
  text "1" at 336.663,46.3 h0.9
  text "3" at 353.656,46.3 h0.9
  text "X" at 317.157,42.287 h0.9
  text "RoHS" at 320.636,42.287 h0.9
  text "OTHER" at 337.003,42.287 h0.9
  text "PER ORDER" at 347.089,42.287 h0.9
  text "ALL BOARDS MUST MEET OR EXCEED UL94-V0 REQUIREMENTS." at 288.252,38.08 h0.9
  text "PCB MUST BEAR THE UL94V-0 UL REGISTERED MATERIAL ID NUMBER" at 288.252,35.032 h0.9
  text "ADDITIONAL REQUIREMENTS:" at 287.552,30.629 h0.9
  text "MICROSECTION:" at 289.451,27.708 h0.9
  text "YES" at 312.457,27.708 h0.9
  text "REQUIRED" at 334.339,23.742 h0.9
  text "BARE BOARD ELEC. TEST:" at 289.451,23.669 h0.9
  text "NONE" at 322.617,23.669 h0.9
  text "X" at 331.113,23.669 h0.9
  text "PER ORDER" at 349.376,23.669 h0.9
  text ".Layer_Name" at 14.465,-22.689 h0.9
M11 Gerber Information:
  lines w0.254: -7.608,-24.51 160.032,-24.51 ; -7.608,-19.345 160.083,-19.345 ; -7.608,-14.181 -7.608,-29.675 94.119,-29.675 160.083,-29.675 160.083,-14.181 -7.595,-14.181 -7.595,-29.675 32.423,-29.675 ; 55.003,-29.675 55.003,-14.181 ; 87.185,-19.345 87.185,-14.181 ; 108.521,-19.345 108.521,-14.181 ; 124.32,-29.84 124.32,-24.688
  text "ALL ARTWORK VIEWED FROM TOP SIDE" at -5.995,-17.538 h0.9
  text "BOARD #:" at 56.908,-17.538 h0.9
  text ".PRJ_Number" at 70.764,-17.538 h0.9
  text "REV:" at 92.214,-17.538 h0.9
  text ".PCB_Rev" at 99.619,-17.538 h0.9
  text "SVN REV:" at 113.5,-17.538 h0.9
  text ".VersionControl_RevNumber" at 126.352,-17.538 h0.9
  text "LAYER NAME =" at -5.995,-22.689 h0.9
  text "TID #:" at 56.908,-22.702 h0.9
  text ".TID" at 70.764,-22.702 h0.9
  text "PLOT NAME =" at -5.995,-27.918 h0.9
  text ".plot_File_Name" at 14.465,-27.918 h0.9
  text "GENERATED    :" at 56.959,-27.918 h0.9
  text ".Print_Date" at 79.045,-27.918 h0.9
  text ".Print_Time" at 97.561,-27.918 h0.9
  text "TEXAS INSTRUMENTS" at 129.679,-27.918 h0.9
M12 Stackup:
  drawing of 295 lines, arcs and shapes, not listed
  text "Layer" at 248.31,190.933 h0.9
  text "Name" at 254.667,190.933 h0.9
  text "Material" at 268.821,190.933 h0.9
  text "Thickness" at 281.926,190.933 h0.9
  text "Constant" at 291.881,190.933 h0.9
  text "Board Layer Stack" at 300.637,190.933 h0.9
  text "Top Overlay" at 254.667,189.133 h0.9
  text "Top Solder" at 254.667,187.333 h0.9
  text "Solder Resist" at 268.821,187.333 h0.9
  text "0,40mil" at 281.926,187.333 h0.9
  text "3,5" at 291.881,187.333 h0.9
  text "1" at 248.31,185.533 h0.9
  text "Top Layer" at 254.667,185.533 h0.9
  text "Copper" at 268.821,185.533 h0.9
  text "1,40mil" at 281.926,185.533 h0.9
  text "Dielectric 1" at 254.667,183.733 h0.9
  text "PP-006" at 268.821,183.733 h0.9
  text "2,80mil" at 281.926,183.733 h0.9
  text "4,1" at 291.881,183.733 h0.9
  text "2" at 248.31,181.933 h0.9
  text "Layer 1" at 254.667,181.933 h0.9
  text "Copper" at 268.821,181.933 h0.9
  text "1,38mil" at 281.926,181.933 h0.9
  text "Dielectric1" at 254.667,180.133 h0.9
  text "FR-4" at 268.821,180.133 h0.9
  text "59,20mil" at 281.926,180.133 h0.9
  text "4,8" at 291.881,180.133 h0.9
  text "3" at 248.31,178.333 h0.9
  text "Layer 2" at 254.667,178.333 h0.9
  text "Copper" at 268.821,178.333 h0.9
  text "1,38mil" at 281.926,178.333 h0.9
  text "Dielectric 2" at 254.667,176.533 h0.9
  text "PP-006" at 268.821,176.533 h0.9
  text "2,80mil" at 281.926,176.533 h0.9
  text "4,1" at 291.881,176.533 h0.9
  text "4" at 248.31,174.733 h0.9
  text "Bottom Layer" at 254.667,174.733 h0.9
  text "Copper" at 268.821,174.733 h0.9
  text "1,40mil" at 281.926,174.733 h0.9
  text "Bottom Solder" at 254.667,172.933 h0.9
  text "Solder Resist" at 268.821,172.933 h0.9
  text "0,40mil" at 281.926,172.933 h0.9
  text "3,5" at 291.881,172.933 h0.9
  text "Bottom Overlay" at 254.667,171.133 h0.9
  text ".Layer_Name" at 14.465,-22.689 h0.9
M13 Component Bodies Top:
  text ".Layer_Name" at 14.465,-22.689 h0.9
M14 Component Bodies Bottom:
  text ".Layer_Name" at 14.465,-22.689 h0.9
M15 Courtyards Top:
  text ".Layer_Name" at 14.465,-22.689 h0.9
M16 Courtyards Bottom:
  text ".Layer_Name" at 14.465,-22.689 h0.9
Drill Drawing:
  text ".Layer_Name" at 14.465,-22.689 h0.9
V-Cut:
  lines w0.254: 29.972,51.435 89.154,51.435 ; 29.972,98.933 89.154,98.933

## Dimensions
89.154,3.937 to 29.972,3.937 on M2 Board Dimensions
-0.191,-11.044 to 25.209,-11.044 on M2 Board Dimensions
29.972,3.937 to 29.972,146.431 on M2 Board Dimensions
